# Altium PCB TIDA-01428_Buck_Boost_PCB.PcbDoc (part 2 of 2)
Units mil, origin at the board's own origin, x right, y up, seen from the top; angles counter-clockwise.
Board outline 4000 x 3000 mil, 2 copper layers (Top Layer, Bottom Layer), stack 62 mil thick; 127 components, 76 nets, 360 pads, 338 vias.
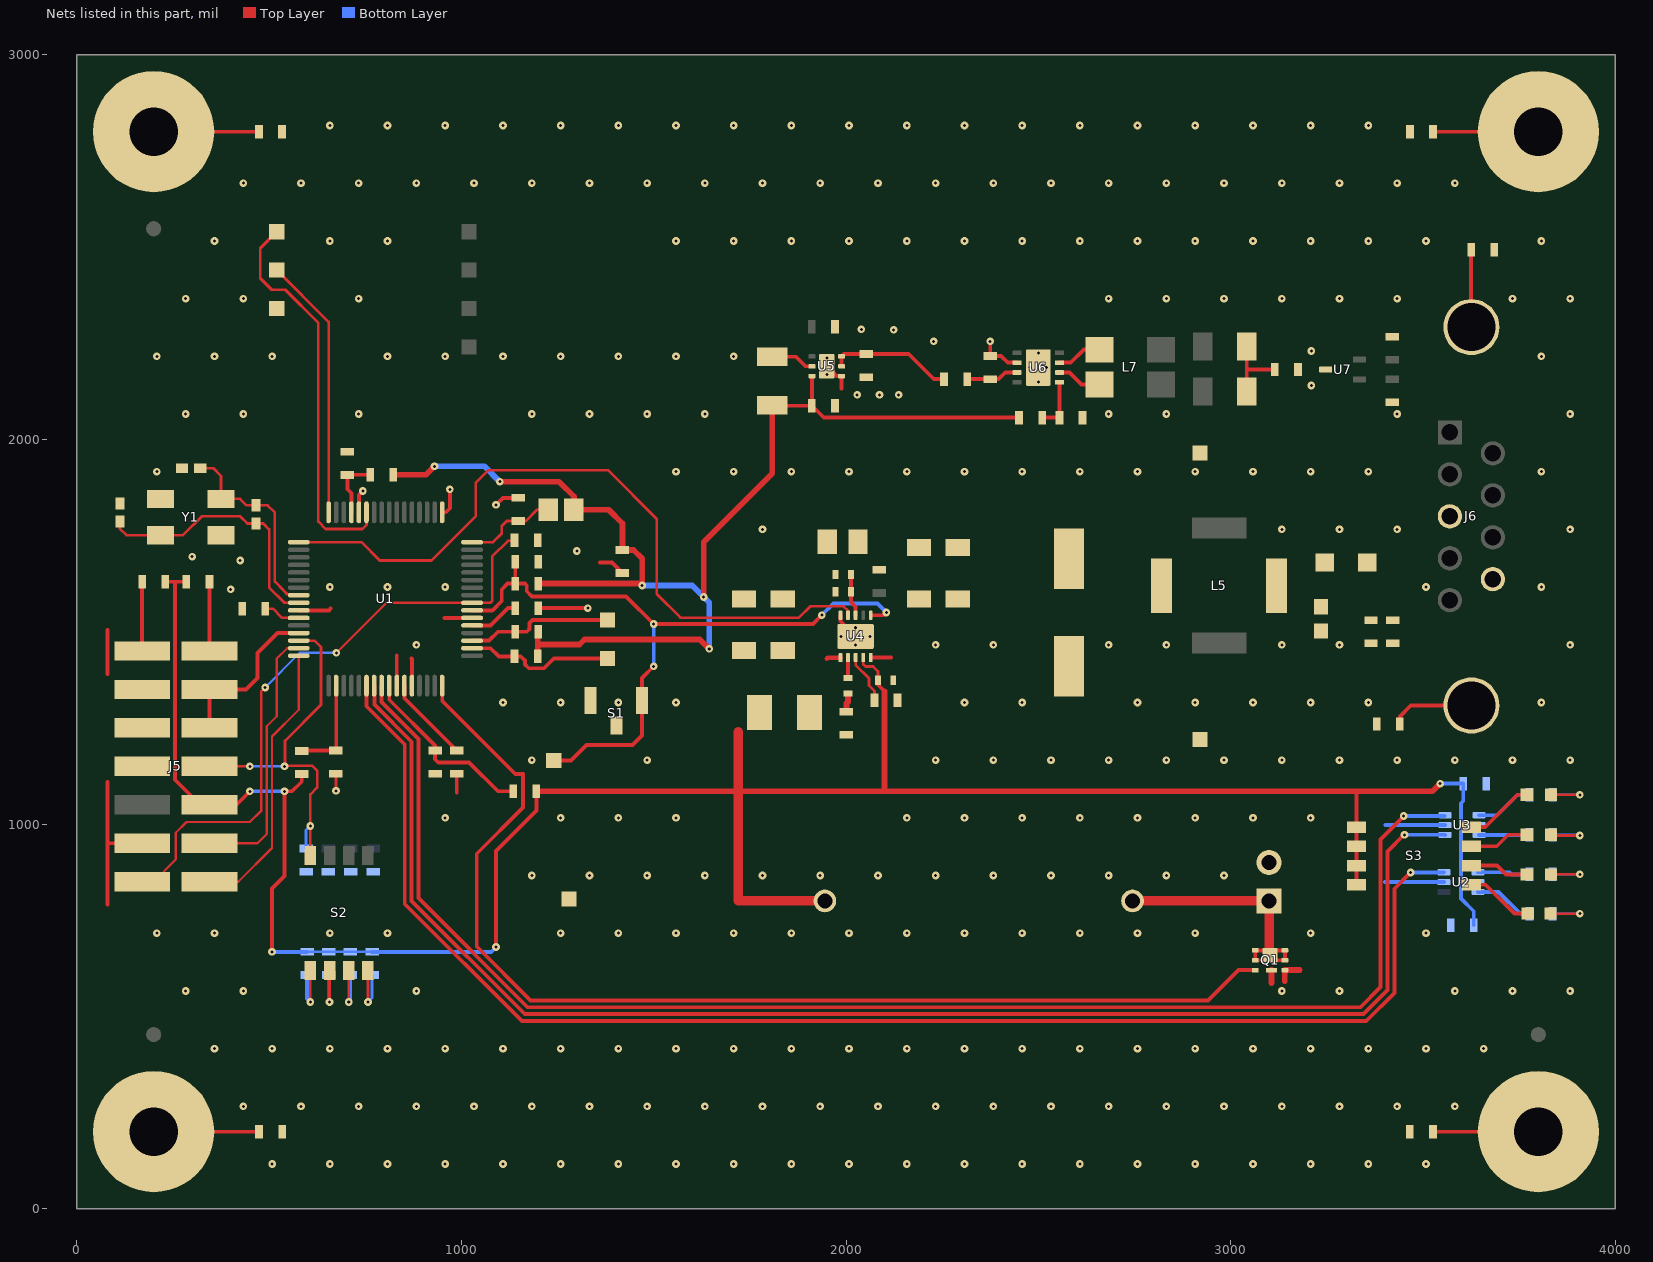
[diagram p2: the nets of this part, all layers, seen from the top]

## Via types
v1: diameter 20, hole 7.87, Top Layer to Bottom Layer, tented both sides, 328 vias
v2: diameter 19.68, hole 7.87, Top Layer to Bottom Layer, 10 vias

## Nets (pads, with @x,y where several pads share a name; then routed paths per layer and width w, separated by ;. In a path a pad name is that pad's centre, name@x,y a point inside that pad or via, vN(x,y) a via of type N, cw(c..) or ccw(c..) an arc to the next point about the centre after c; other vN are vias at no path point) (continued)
GND: C1.2 C2.2 C3.2 C4.2 C5.2 C6.2 C7.2 C8.2 C9.2 C10.2 C11.2 C13.2 C14.2 C15.2 C16.2 C17.2 C18.2 C19.2 C20.2 C21.2 C22.2 C23.2 C24.2 C25.2 C26.2 C27.2 C28.2 C29.2 C30.2 C31.2 C36.2 C37.2 J5.4 J5.8 J5.10 J5.12 J6.3 J7.2 Q1.4 Q1.7 R8.1 R9.1 R10.1 R11.1 R19.1 R20.2 R27.1 R28.1 R30.2 R31.2 R32.2 R33.2 R34.2 S1.2 S1.3 TP10.1 TP11.1 TP12.1 TP13.1 U1.6 U1.17 U1.28 U1.42 U1.58 U1.60 U2.2 U3.2 U4.5 U4.10 U4.11@2025,1487.64 U5.1 U5.7@1950,2190 U6.2 U6.9@2500,2186.69 U7.3 Y1.2 Y1.4 | length 2291.9
  Top Layer w7: v1(673.81,1086.19) R8.1@673.81,1130.91
  Top Layer w10: 80,790.25 80,950 ; 80,1110 80,950 ; 80,1390 80,1505 ; J5.4@170,950 80,950 ; U1.42@577.11,1555.54 655.54,1555.54 660,1560 ; U1.28@733.6,1810.46 733.6,1855.44 v1(743.79,1865.63) ; U1.58@832.03,1359.67 832.03,1437.97 ; 870,1430 871.4,1428.6 U1.60@871.4,1359.67 ; U1.17@950.14,1810.46 959.54,1810.46 970,1820.92 v1(970,1870) ; 955.85,1535.85 U1.6@1027.89,1535.85 ; 987.81,1082.19 C6.2@987.81,1130.91 ; v1(1090,1830) 1108,1848 C5.2@1148,1848 ; C8.2@1200,1561.31 v1(1328.69,1561.31) ; 1360,1680 1391.25,1680 C1.2@1418.75,1652.5 ; U5.7@1950,2190 1975.59,2164.41 U5.1@1988.39,2164.41 1988.39,2131.61 ; U4.10@1985.63,1542.76 1985.63,1527.01 U4.11@2025,1487.64 ; U4.5@2064.37,1432.52 2117.48,1432.52 ; v1(2375,2255) C28.2@2375,2216.69 2403.31,2216.69 2420.51,2199.49 U6.2@2444.88,2199.49
  Top Layer w15: 3106.35,586.35 Q1.7@3106.35,620.19 ; 3140.99,590.99 Q1.4@3140.99,620.19 3179.81,620.19
  Bottom Layer w10: v2(1987.6,1487.64) 2025,1487.64 ; v2(2025,1465) 2025,1487.64 ; v2(2025,1510.28) 2025,1487.64 ; v2(2062.4,1487.64) 2025,1487.64 ; v2(2478.35,2186.69) 2500,2186.69 ; v2(2500,2149.29) 2500,2186.69 ; v2(2500,2224.09) 2500,2186.69 ; v2(2521.65,2186.69) 2500,2186.69 ; 3401,849 U2.2@3554.71,849 ; 3402.19,997.19 U3.2@3557.62,997.19
  other v1: 508,116 658,116 808,116 958,116 1108,116 1258,116 1408,116 1558,116 1708,116 1858,116 2008,116 2158,116 2308,116 2458,116 2608,116 2758,116 2908,116 3058,116 3208,116 3358,116 3508,116 433,266 583,266 733,266 883,266 1033,266 1183,266 1333,266 1483,266 1633,266 1783,266 1933,266 2083,266 2233,266 2383,266 2533,266 2683,266 2833,266 2983,266 3133,266 3283,266 3433,266 3583,266 358,416 508,416 658,416 808,416 958,416 1108,416 1258,416 1408,416 1558,416 1708,416 1858,416 2008,416 2158,416 2308,416 2458,416 2608,416 2758,416 2908,416 3058,416 3208,416 3358,416 3508,416 3658,416 283,566 433,566 883,566 3133,566 3283,566 3583,566 3733,566 3883,566 208,716 358,716 658,716 808,716 1258,716 1408,716 1558,716 1708,716 1858,716 2008,716 2158,716 2308,716 2458,716 2608,716 2758,716 2908,716 3208,716 3508,716 1183,866 1333,866 1483,866 1633,866 1783,866 1933,866 2083,866 2233,866 2383,866 2533,866 2683,866 2833,866 2983,866 958,1016 1258,1016 1408,1016 1558,1016 2158,1016 2308,1016 2458,1016 2608,1016 2758,1016 2908,1016 3058,1016 3208,1016 1183,1166 1483,1166 2233,1166 2383,1166 2533,1166 2683,1166 2833,1166 2983,1166 3133,1166 3283,1166 3433,1166 3583,1166 3733,1166 3883,1166 1108,1316 1258,1316 1408,1316 1558,1316 2308,1316 2458,1316 2758,1316 2908,1316 3058,1316 3208,1316 3358,1316 3808,1316 883,1466 2233,1466 2383,1466 2683,1466 2833,1466 3133,1466 3283,1466 3883,1466 400,1610 658,1616 808,1616 958,1616 3508,1616 3808,1616 425,1685 300,1695 1300,1710 1783,1766 3133,1766 3283,1766 3433,1766 3883,1766 208,1916 1558,1916 1708,1916 1858,1916 2008,1916 2158,1916 2308,1916 2458,1916 2608,1916 2758,1916 2908,1916 3058,1916 3208,1916 3358,1916 3808,1916 283,2066 433,2066 733,2066 1183,2066 1333,2066 1483,2066 1633,2066 2683,2066 2833,2066 3433,2066 3883,2066 2029,2116 2087,2116 2137,2116 3210,2140 208,2216 358,2216 508,2216 808,2216 958,2216 1108,2216 1258,2216 1408,2216 1558,2216 1708,2216 3808,2216 3210,2230 2228,2255 2124,2285 2040,2286 283,2366 433,2366 733,2366 2683,2366 2833,2366 2983,2366 3133,2366 3283,2366 3433,2366 3733,2366 3883,2366 358,2516 658,2516 808,2516 1558,2516 1708,2516 1858,2516 2008,2516 2158,2516 2308,2516 2458,2516 2608,2516 2758,2516 2908,2516 3058,2516 3208,2516 3358,2516 3508,2516 3808,2516 433,2666 583,2666 733,2666 883,2666 1033,2666 1183,2666 1333,2666 1483,2666 1633,2666 1783,2666 1933,2666 2083,2666 2233,2666 2383,2666 2533,2666 2683,2666 2833,2666 2983,2666 3133,2666 3283,2666 3433,2666 3583,2666 658,2816 808,2816 958,2816 1108,2816 1258,2816 1408,2816 1558,2816 1708,2816 1858,2816 2008,2816 2158,2816 2308,2816 2458,2816 2608,2816 2758,2816 2908,2816 3058,2816 3208,2816 3358,2816
  other v2: 1950,2168.35 1950,2211.65
GREEN_LED: U1.54 U2.3 | length 3755.3
  Top Layer w10: U1.54@753.29,1359.67 753.29,1306.16 852.87,1206.57 852.87,792.4 1157.4,487.87 3352.6,487.87 3425.75,561.03 3425.75,831.75 v1(3468,874)
  Bottom Layer w10: v1(3468,874) 3554.12,874 U2.3@3554.71,874.59
I2C_SCL: R13.1 TP8.1 U1.3 | length 548.5
  Top Layer w10: U1.3@1027.89,1476.7 1071.7,1476.7 1095,1500 R13.1@1140,1500 1170,1500 1177.13,1507.13 1177.13,1522.83 1184.67,1530.37 1215.33,1530.37 ; 1215.33,1530.37 1215.71,1530 TP8.1@1380,1530 1379.63,1530.37 1215.33,1530.37
I2C_SDA: R12.1 TP7.1 U1.2 | length 389.9
  Top Layer w10: U1.2@1027.89,1457.11 1075.89,1457.11 1097.39,1435.61 R12.1@1138.31,1435.61 1154.39,1435.61 1165,1425 1165,1415 1175,1405 1215,1405 1240,1430 TP7.1@1380,1430
MASTER_SELECT: R5.1 R8.2 U1.50 | length 255.9
  Top Layer w10: R5.1@585.91,1190.91 R8.2@673.81,1190.91 ; R8.2@674.55,1191.64 U1.50@674.55,1359.67
NetC3_1: C3.1 L1.1 U1.57 | length 478.6
  Top Layer w10: U1.57@812.34,1359.67 812.34,1322.94 931.5,1203.78 C3.1@931.5,1190.91 931.5,1168.5 940,1160 1020,1160 1095,1085 L1.1@1135,1085
NetC4_1: C4.1 L2.1 U1.29 | length 160.7
  Top Layer w10: U1.29@713.92,1810.46 713.92,1860.08 703.75,1870.25 C4.1@703.75,1907.5 704.25,1908 L2.1@763,1908
NetC5_1: C5.1 L3.1 U1.16 | length 244.3
  Top Layer w7: U1.16@1027.89,1732.7 1082.7,1732.7 1105,1755 1105,1775 1118,1788 C5.1@1148,1788 1168,1788 1197,1817 L3.1@1225.54,1817
NetC6_1: C6.1 U1.59 | length 225.1
  Top Layer w10: U1.59@851.71,1359.67 851.71,1327 C6.1@987.81,1190.91
NetC7_1: C7.1 U1.43 | length 97.1
  Top Layer w7: C7.1@490,1560 510,1560 534.15,1535.85 U1.43@577.11,1535.85
NetC8_1: C8.1 U1.5 | length 130.8
  Top Layer w10: U1.5@1027.89,1516.07 1076.07,1516.07 1121.31,1561.31 C8.1@1140,1561.31
NetC10_1: C10.1 R16.2 U1.41 Y1.1 | length 692.4
  Top Layer w7: C10.1@112.5,1786.38 112.5,1767.5 129.09,1750.91 Y1.1@217.49,1750.91 275.91,1750.91 325,1800 425,1800 443.62,1781.38 R16.2@466.39,1781.38 484.87,1781.38 500.13,1766.12 500.13,1614.87 539.78,1575.22 U1.41@577.11,1575.22
NetC11_1: C11.1 R16.1 U1.40 Y1.3 | length 533.3
  Top Layer w7: C11.1@321.12,1925 355,1925 374.97,1905.03 Y1.3@374.97,1845.4 424.6,1845.4 441.38,1828.62 R16.1@466.39,1828.62 496.38,1828.62 515,1810 515,1630 537.19,1607.81 537.19,1607.44 547.31,1597.31 574.7,1597.31 U1.40@577.11,1594.91
NetC12_1: C12.1 R35.2 | length 48.9
  Top Layer w15: C12.1@2001,1292 2001,1313 2005,1317 R35.2@2005,1339.26
NetC12_2: C12.2 L6.1 U4.1 | length 36.7
  Top Layer w12: 1950,1430 1952.52,1432.52 U4.1@1985.63,1432.52
NetC15_1: C15.1 D5.1 L5.1
NetC19_1: C19.1 U4.3 | length 130.9
  Top Layer w7: U4.3@2025,1432.52 2025,1413.97 2060,1378.97 2060,1360 2073.98,1346.02 C19.1@2073.98,1321.89
NetC27_1: C27.1 R23.1 R24.2 | length 188.8
  Top Layer w10: R24.2@3042.09,2124.45 R23.1@3042.09,2241.69 ; 3043.46,2181.69 C27.1@3115,2181.69
NetC28_1: C28.1 R21.2 U6.3 | length 137
  Top Layer w10: R21.2@2315,2156.69 C28.1@2375,2156.69 2396.69,2156.69 2413.9,2173.9 U6.3@2444.88,2173.9
NetC29_1: C29.1 R22.2 U6.5 | length 136.7
  Top Layer w10: R22.2@2510,2056.69 C29.1@2555,2056.69 2555.12,2056.81 U6.5@2555.12,2148.31
NetD1_1: D1.1 S3.1 | length 177.1
  Top Layer w10: S3.1@3626.41,842 3663,842 3738,767 D1.1@3772.47,767
NetD1_2: D1.2 R1.2 | length 147.4
  Top Layer w7: D1.2@3831.53,767 v1(3908,767)
  Bottom Layer w7: R1.2@3837.07,767 v1(3908,767)
NetD2_1: D2.1 R2.2 | length 145.9
  Top Layer w7: D2.1@3833.06,868.99 v1(3908,869)
  Bottom Layer w7: R2.2@3837.07,869 v1(3908,869)
NetD2_2: D2.2 S3.2 | length 153.2
  Top Layer w10: S3.2@3626.41,892 3693,892 3716.01,868.99 D2.2@3770.07,868.99
NetD3_1: D3.1 R3.2 | length 144.7
  Top Layer w7: D3.1@3835.06,970 v1@3905,970 ; v1@3907,972 v1@3905,970 ; v1(3908,970) v1@3905,970
  Bottom Layer w7: R3.2@3837.07,972 v1@3906,972
NetD3_2: D3.2 S3.3 | length 156.1
  Top Layer w10: S3.3@3626.41,942 3692,942 3722,972 D3.2@3770.07,972
NetD4_1: D4.1 R4.2 | length 145.9
  Top Layer w7: D4.1@3833.06,1076 v1(3908,1076)
  Bottom Layer w7: R4.2@3837.07,1076.01 v1(3908,1076)
NetD4_2: D4.2 S3.4 | length 178.5
  Top Layer w10: S3.4@3626.41,992 3662,992 3746,1076 D4.2@3770.07,1076
NetH1_1: H1.1 R31.1 | length 273.8
  Top Layer w10: H1.1@200,2800 R31.1@473.75,2800
NetH2_1: H2.1 R32.1 | length 273.8
  Top Layer w10: R32.1@3526.25,2800 H2.1@3800,2800
NetH3_1: H3.1 R33.1 | length 273.8
  Top Layer w10: H3.1@200,200 R33.1@473.75,200
NetH4_1: H4.1 R34.1 | length 273.8
  Top Layer w10: R34.1@3526.25,200 H4.1@3800,200
NetJ5_13: J5.13 R14.1 | length 180
  Top Layer w10: J5.13@345,1450 R14.1@345,1630
NetJ5_14: J5.14 R15.1 | length 180
  Top Layer w10: J5.14@170,1450 R15.1@170,1630
NetJ6_10: J6.10 R20.1 | length 199.7
  Top Layer w10: J6.10@3625,2292.91 R20.1@3625,2492.57
NetJ6_11: J6.11 R30.1 | length 217.4
  Top Layer w10: R30.1@3440.11,1260 3440.11,1279.89 3468.29,1308.07 J6.11@3625.98,1308.07
NetJ7_1: J7.1 Q1.1 Q1.2 Q1.5 Q1.6 Q1.8 R29.1 | length 688.4
  Top Layer w10: Q1.2@3064.22,645.78 Q1.5@3140.99,645.78 Q1.6@3140.99,671.37 3100,671.37 Q1.1@3064.22,671.37 Q1.2@3064.22,645.78
  Top Layer w25: R29.1@2745,800 J7.1@3100,800 Q1.8@3100,671.37
NetL4_2: L4.2 U5.5 | length 113.4
  Top Layer w10: L4.2@1808.48,2214.85 1870.15,2214.85 1895,2190 U5.5@1911.61,2190
NetL7_1: L7.1 U6.6 | length 116.9
  Top Layer w10: U6.6@2555.12,2173.9 2581.1,2173.9 2612.19,2142.81 L7.1@2659.17,2142.81
NetL7_4: L7.4 U6.7 | length 118.1
  Top Layer w10: U6.7@2555.12,2199.49 2584.49,2199.49 2618.36,2233.36 L7.4@2659.17,2233.36
NetR1_1: R1.1 U2.6 | length 157.1
  Bottom Layer w10: U2.6@3643.29,823.4 3696.6,823.4 3753,767 R1.1@3777.07,767
NetR2_1: R2.1 U2.4 | length 136.1
  Bottom Layer w10: U2.4@3643.29,874.59 3725.41,874.59 3731,869 R2.1@3777.07,869
NetR3_1: R3.1 U3.6 | length 131
  Bottom Layer w10: U3.6@3646.21,971.6 3776.67,971.6 R3.1@3777.07,972
NetR4_1: R4.1 U3.4 | length 152.9
  Bottom Layer w10: U3.4@3646.21,1022.78 3692.78,1022.78 3746.01,1076.01 R4.1@3777.07,1076.01
NetR6_1: R6.1 S2.8 | length 156.9
  Top Layer w7: v1(757.18,537.18) S2.8@757.18,619.41
  Bottom Layer w7: v1(757.18,537.18) 767.8,547.8 R6.1@767.8,607.51
NetR7_1: R7.1 S2.7 | length 154.3
  Top Layer w7: v1(707.18,537.18) S2.7@707.18,619.41
  Bottom Layer w7: v1(707.18,537.18) 711.49,541.49 R7.1@711.49,607.51
NetR25_1: R25.1 S2.6 | length 153.4
  Top Layer w7: v1(657.18,537.18) S2.6@657.18,619.41
  Bottom Layer w7: R25.1@655.18,607.51 655.18,539.19 v1(657.18,537.18)
NetR26_1: R26.1 S2.5 | length 156
  Top Layer w7: v1(607.18,537.18) S2.5@607.18,619.41
  Bottom Layer w10: R26.1@598.87,607.51 598.87,545.5 v1(607.18,537.18)
NetR35_1: R35.1 U4.2 | length 53.3
  Top Layer w10: R35.1@2005,1379.26 U4.2@2005.31,1432.52
NRST: C37.1 R17.2 S1.1 TP9.1 U1.7 U4.6 | length 1865.4
  Top Layer w10: U1.7@1027.99,1555.44 1080.44,1555.44 1105,1580 1105,1610 1120,1625 R17.2@1140,1625 ; C37.1@1140,1680 R17.2@1140,1625 ; TP9.1@1240,1165 1285,1165 1325,1205 1445,1205 1469.93,1229.93 S1.1@1469.93,1321 1469.93,1379.93 v1(1500,1410) ; v1(1937,1543) 1914,1520 v1(1500,1520) 1428.32,1591.68 1183.32,1591.68 1170,1605 1170,1620 1165,1625 R17.2@1140,1625 ; U4.6@2064.37,1542.76 2097.76,1542.76 v1(2105,1550)
  Bottom Layer w10: v1(1500,1410) v1(1500,1520) ; v1(1937,1543) 1967.26,1573.26 2081.74,1573.26 v1(2105,1550)
NTRST: J5.2 R11.2 U1.8 | length 1625.4
  Top Layer w6: J5.2@170,850 200,850 257.5,907.5 257.5,977.5 285,1005 450,1005 480,1035 480,1345 v1(490,1355) ; v1(675,1445) 805.22,1575.22 U1.8@1027.89,1575.22
  Top Layer w7: U1.8@1027.89,1575.22 1075.22,1575.22 1080,1580 1080,1695 1121.31,1736.31 R11.2@1138.31,1736.31
  Bottom Layer w6: v1(490,1355) 580,1445 v1(675,1445)
Q1_GATE: Q1.3 U1.64 | length 2941.6
  Top Layer w10: U1.64@950.14,1359.67 950.14,1319.86 1140,1130 1160,1130 1160,1042.79 1040,922.79 1040,681.11 1179.61,541.5 2941.5,541.5 3020.19,620.19 Q1.3@3064.22,620.19
RED_LED: U1.55 U3.1 | length 3813.5
  Top Layer w10: U1.55@772.97,1359.67 773.88,1358.77 773.88,1310.84 870.75,1213.97 870.75,799.81 1164.81,505.75 3345.19,505.75 3407.87,568.43 3407.87,928.87 3451,972 v1(3452,972)
  Bottom Layer w10: v1(3452,972) 3557.22,972 U3.1@3557.62,971.6
SYNC: U1.33 U4.9 | length 1898.3
  Top Layer w7: U1.33@577.11,1732.7 740,1732.7 787.7,1685 922,1685 1037,1800 1037,1887 1070,1920 1381,1920 1508,1793 1508,1598 1569.63,1536.37 1877.37,1536.37 1907,1566 1994.05,1566 2005.32,1554.74 U4.9@2005.32,1542.76
TCK: J5.9 J5.11 U1.45 | length 430.9
  Top Layer w10: J5.9@345,1250 J5.11@345,1350 440,1350 470,1380 470,1445 521.48,1496.48 U1.45@577.11,1496.48
TDI: J5.3 U1.47 | length 694
  Top Layer w6: J5.3@345,950 470,950 493.87,973.87 493.87,1253.87 520,1280 520,1430 547.11,1457.11 U1.47@577.11,1457.11
TDO: J5.7 R28.2 S2.4 U1.46 | length 989.5
  Top Layer w7: J5.7@345,1150 v1(450,1150) ; v1(540,1150) v1@541.25,1151.25 ; U1.46@577.11,1476.8 618.2,1476.8 635,1460 635,1310 541.25,1216.25 v1@541.25,1151.25 ; S2.4@607.18,918.23 v1(607.18,995) 607.18,1077.18 625,1095 625,1138.75 612.38,1151.37 541.37,1151.37 v1@541.25,1151.25
  Bottom Layer w7: v1(450,1150) v1(540,1150) ; R28.2@596.18,936.14 596.18,984 v1(607.18,995)
TMS: J5.1 U1.48 | length 727.5
  Top Layer w6: J5.1@345,850 420,850 507.75,937.75 507.75,1227.75 577.11,1297.11 U1.48@577.11,1437.43
UART_RX: TP3.1 U1.32 | length 685.4
  Top Layer w7: TP3.1@520,2440 654.86,2305.14 U1.32@654.86,1810.46
UART_TX: TP4.1 U1.27 | length 1025.4
  Top Layer w7: TP4.1@520,2540 477,2497 477,2419 507,2389 542,2389 628,2303 628,1786 647,1767 743,1767 753.29,1777.29 U1.27@753.29,1810.46
V3P3: C1.1 C2.1 C9.1 C20.1 C21.1 C22.1 C24.1 J5.5 L1.2 L2.2 L3.2 L4.1 L6.2 R5.2 R6.2 R7.2 R12.2 R13.2 R14.2 R15.2 R17.1 R22.1 R25.2 R26.2 R29.2 S3.5 S3.6 S3.7 S3.8 U2.5 U3.5 U4.4 U5.6 | length 9909.3
  Top Layer w7: U4.4@2044.68,1432.52 2044.68,1415.32 2050.67,1409.33 2070.67,1409.33 2082.96,1397.04 C24.1@2082.96,1373.97
  Top Layer w10: R15.2@230,1630 255,1630 ; R14.2@285,1630 255,1630 ; v1(450,1085) 415,1050 J5.5@345,1050 320.32,1050 255.32,1115 255.32,1480.65 255,1480.96 255,1630 ; v1(507.49,667.51) 507.49,832.49 540,865 v1(540,1085) 560,1085 585,1110 R5.2@585,1130 ; v1(1090,680) 1090,930 1195,1035 L1.2@1195,1085 ; L4.1@1809.85,2087.5 C22.1@1911.25,2087.5 ; U5.6@1911.61,2164.41 1911.61,2087.86 C22.1@1911.25,2087.5 ; C24.1@2082.96,1373.97 2082.96,1362.04 2100,1345 ; R22.1@2450,2056.69 1942.06,2056.69 C22.1@1911.25,2087.5 ; S3.8@3327.59,842 S3.7@3327.59,892 S3.6@3327.59,942 S3.5@3327.59,992 3327.59,1085
  Top Layer w15: L2.2@823,1908 908,1908 v1(930,1930) ; v1(1100,1890) 1254.1,1890 1292.46,1851.64 L3.2@1292.46,1817 1383,1817 1418.75,1781.25 C1.1@1418.75,1712.5 1447.5,1712.5 1470,1690 v1@1470,1625 ; L1.2@1195,1085 1715.08,1085 ; R12.2@1198.31,1435.61 1198.31,1466.96 ; R13.2@1198.31,1498.31 1198.31,1466.96 ; R17.1@1200,1625 v1@1470,1625 ; v1(1470,1620) v1@1470,1625 ; v1(1630,1590) 1630,1733.03 1808.48,1911.52 L4.1@1808.48,2088.87 ; v1(1644.42,1455.58) 1620,1480 1320,1480 1306.96,1466.96 1198.31,1466.96 ; 1720.08,1085 2100,1085 ; 2100,1345 2100,1085 ; v1(3545,1105) 3525,1085 3327.59,1085 2100,1085
  Top Layer w25: 1720.08,1239.92 1720.08,1085 1720.08,800 R29.2@1945,800
  Bottom Layer w7: R26.2@598.87,667.51 R25.2@655.18,667.51 R7.2@711.49,667.51 R6.2@767.8,667.51
  Bottom Layer w10: v1(450,1085) v1(540,1085) ; v1(507.49,667.51) R26.2@598.87,667.51 ; R6.2@767.8,667.51 1077.51,667.51 v1(1090,680) ; v1(3545,1105) C2.1@3605,1105 3605,1060 3599,1054 3599,999.37 ; 3599,997.19 3599,849 ; 3601.19,997.19 U3.5@3646.21,997.19 ; C9.1@3632,737 3632,773 3599,806 3599,849 ; U2.5@3643.29,849 3599,849
  Bottom Layer w15: v1(930,1930) 1060,1930 v1(1100,1890) ; v1(1470,1620) 1600,1620 v1(1630,1590) 1644.42,1575.58 v1(1644.42,1455.58)
V5P0: C23.1 R21.1 U5.2 U5.3 | length 321.8
  Top Layer w10: U5.2@1988.39,2190 U5.3@1988.39,2215.59 1994.66,2221.86 C23.1@2052.31,2221.86 2163.14,2221.86 2228.31,2156.69 R21.1@2255,2156.69
VBATT: C14.1 C36.1 D5.2 J6.9
VBATT_FILT: C13.1 C16.1 C17.1 C18.1 C25.1 C31.1 L5.3 R18.2 U4.8 | length 110.8
  Top Layer w10: C25.1@2013,1648.5 2012.82,1577.18 2025,1565 U4.8@2025,1542.76
YELLOW_LED: U1.56 U3.3 | length 3810
  Top Layer w10: U1.56@792.66,1359.67 792.66,1317.34 888.62,1221.38 888.62,807.21 1172.21,523.62 3337.79,523.62 3390,575.83 3390,960 3451,1021 v1(3450,1021)
  Bottom Layer w10: v1(3450,1021) U3.3@3555.85,1021
pads on no net: FID1.1 FID2.1 FID3.1 J5.6 J6.1 J6.4 J6.5 J6.6 J6.8 L5.2 L5.4 Q1.0 U1.1 U1.4 U1.9 U1.10 U1.11 U1.12 U1.13 U1.14 U1.15 U1.18 U1.19 U1.20 U1.21 U1.22 U1.23 U1.24 U1.30 U1.31 U1.36 U1.37 U1.38 U1.39 U1.44 U1.51 U1.62 U1.63 U4.11@1964.76,1477.8 U4.11@1964.76,1497.48 U4.11@2000.2,1487.64 U4.11@2049.8,1487.64 U4.11@2085.24,1477.8 U4.11@2085.24,1497.48 U5.7@1950,2172.28 U5.7@1950,2207.72 U6.9@2500,2161.69 U6.9@2500,2211.69

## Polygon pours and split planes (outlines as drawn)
GND on Bottom Layer "Bottom Layer-No Net" (solid, pour order 0): 75,75 3925,75 3925,2925 75,2925 75,75
V3P3 on Top Layer "V3p3_Pour" (solid, pour order 12): 2140,1050 2140,1200 1830,1200 1830,1350 1910,1430 1910,1490 1610,1490 1610,1050
GND on Top Layer "TOP_LAYER_GND_P014" (solid, pour order 14): 75,75 3925,75 3925,2925 75,2925 75,75
VBATT on Top Layer "Top Layer-No Net" (solid, pour order 4): 3315,1490 3315,1730 3420,1730 3420,1640 3500,1530 3620,1530 3620,1700 3760,1700 3760,1490
NetC15_1 on Top Layer "Top Layer-No Net 1" (solid, pour order 6): 3295,1730 3295,1525 3050,1525 3050,1730
VBATT_FILT on Top Layer "Top Layer-No Net 2" (solid, pour order 8): 2890,1820 2890,1530 2520,1530 2290,1680 2130,1680 2130,1640 2060,1640 2060,1620 2060,1577.18 1999,1577.18 1999,1820
NetC12_2 on Top Layer "Top Layer-No Net 3" (solid, pour order 10): 1964.96,1460 2000,1460 2000,1402.64 1984.36,1387 1984.36,1360 2050,1360 2050,1202 1850,1202 1850,1350

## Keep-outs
Keep-Out Layer:
  text ".Layer_Name" at 577,-858.49 h60

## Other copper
Top Layer:
  text ".Layer_Name" at 577,-858.49 h60
Bottom Layer:
  text ".Layer_Name" at 577,-858.49 h60

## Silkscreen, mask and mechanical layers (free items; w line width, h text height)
Top Overlay:
  region: 1600,2850 1300,2850 1300,2750 1600,2750
  lines w7: 60,2060 1560,2060 ; 1650,1030 3200,1030 ; 1650,1810 2340,1810 ; 1650,2380 2180,2380 ; 2210,2380 3460,2380 ; 2380,1810 3460,1810 ; 3250,690 3975,690 ; 3755,737 3875,737 3875,797 3755,797 ; 3864,737 3864,797 ; 3870,737 3870,797 ; 60,570 60,2180 1560,2180 1560,570 60,570 ; 1650,570 3200,570 3200,1150 1650,1150 1650,570 ; 1650,1171 2340,1171 2340,1930 1650,1930 1650,1171 ; 1650,2000 2180,2000 2180,2500 1650,2500 1650,2000 ; 2210,2000 3460,2000 3460,2500 2210,2500 2210,2000 ; 2380,1311.69 2380,1930 3460,1930 3460,1311.69 2380,1311.69 ; 3250,570 3975,570 3975,1150 3250,1150 3250,570
  text "'.PRJ_Number'.PCB_Rev-" at 600,2765 h108.27
  text "UART_TX" at 570,2520 h40
  text "CAN_STB" at 1070,2520 h40
  text "UART_RX" at 570,2420 h40
  text "CAN_TXD" at 1070,2420 h40
  text "CAN Physical Layer" at 2350,2411.69 h55
  text "5V Boost" at 1710,2410 h55
  text "GND" at 570,2320 h40
  text "CAN_RXD" at 1070,2320 h40
  text "5V_EN" at 1070,2220 h40
  text "C2000 Peripheral Conns." at 150,2100 h60
  text "GND" at 2970,1945 h40
  text "Blocking & Filtering" at 2410,1850 h55
  text "3.3V Buck" at 1730,1840 h60
  text "SCL" at 1430,1510 h40
  text "SDA" at 1430,1410 h40
  text "GND" at 2970,1200 h40
  text "NRST" at 1325.2,1147.16 h40
  text "Closed-Open" at 3275,1080 h40
  text "Load Resistor" at 2110,1060 h60
  text "BM / DR1 / DR2 / TDO" at 800,985 h40 r90
  text "GND" at 1340,785 h40
  text "Status LEDs" at 3300,600 h60
  text "Closed-Open" at 520,585 h40 r90
  text ".Layer_Name" at 577,-858.49 h60
Bottom Overlay:
  text ".Layer_Name" at 577,-858.49 h60
Top Paste:
  text ".Layer_Name" at 577,-858.49 h60
Bottom Paste:
  text ".Layer_Name" at 577,-858.49 h60
Top Solder:
  text ".Layer_Name" at 577,-858.49 h60
  text ".Layer_Name" at 577,-858.49 h60
Bottom Solder:
  text ".Layer_Name" at 577,-858.49 h60
Drill Guide:
  text ".Layer_Name" at 577,-858.49 h60
M1 Board Outline:
  the board outline again, w7
  text ".Layer_Name" at 577,-858.49 h60
M2 Board Dimensions:
  rectangle: 0,-275 125,-150
  rectangle: 125,-400 500,-275
  lines w7: 0,-275 1000,-275 ; 125,-400 125,-150 ; 250,-400 250,-150 ; 500,-400 500,-150 ; 750,-400 750,-150 ; 0,-400 1000,-400 1000,-150 0,-150 0,-400
  text ".Layer_Name" at 577,-858.49 h60
M3 3D STEP Top:
  text ".Layer_Name" at 577,-858.49 h60
M4 3D STEP Bottom:
  text ".Layer_Name" at 577,-858.49 h60
M5 Assembly Top:
  lines w10: -292,-930.17 6308,-930.17 ; -292,-726.83 6310,-726.83 ; -292,-523.5 -292,-1133.5 3713,-1133.5 6310,-1133.5 6310,-523.5 -291.5,-523.5 -291.5,-1133.5 1284,-1133.5 ; 2173,-1133.5 2173,-523.5 ; 3440,-726.83 3440,-523.5 ; 4280,-726.83 4280,-523.5 ; 4902,-1140 4902,-937.17
  text "COMPONENTS MARKED 'DNP' SHOULD NOT BE POPULATED." at 1153.5,-318.5 h60
  text "ASSEMBLY VARIANT:" at 1153,-434 h60
  text ".VariantName" at 2189,-434 h60
  text "PCB VIEWED FROM TOP SIDE" at -228.5,-655.67 h60
  text "BOARD #:" at 2248,-655.67 h60
  text ".PRJ_Number" at 2793.5,-655.67 h60
  text "REV:" at 3638,-655.67 h60
  text ".PCB_Rev" at 3929.5,-655.67 h60
  text "SVN REV:" at 4476,-655.67 h60
  text ".VersionControl_RevNumber" at 4982,-655.67 h60
  text "TID #:" at 2248,-859 h60
  text ".TID" at 2793.5,-859 h60
  text "PLOT NAME =" at -228.5,-1064.34 h60
  text ".plot_File_Name" at 577,-1064.34 h60
  text "GENERATED    :" at 2250,-1064.34 h60
  text ".Print_Date" at 3119.5,-1064.34 h60
  text ".Print_Time" at 3848.5,-1064.34 h60
  text "TEXAS INSTRUMENTS" at 5113,-1064.34 h60
M6 Assembly Bottom:
  lines w10: -292.5,-727.33 6309.5,-727.33 ; -290.5,-930.67 6309.5,-930.67 ; 1115.5,-1140.5 1115.5,-937.67 ; 1737.5,-727.33 1737.5,-524 ; 2577.5,-727.33 2577.5,-524 ; 3844.5,-1134 3844.5,-524 ; 4733.5,-1134 6309,-1134 6309,-524 -292.5,-524 -292.5,-1134 2304.5,-1134 6309.5,-1134 6309.5,-524
  text "COMPONENTS MARKED 'DNP' SHOULD NOT BE POPULATED." at 6102,-318 h60
  text ".VariantName" at 5058,-434 h60
  text "ASSEMBLY VARIANT:" at 6097,-434 h60
  text ".VersionControl_RevNumber" at 1035.5,-656.17 h60
  text "SVN REV:" at 1541.5,-656.17 h60
  text ".PCB_Rev" at 2088,-656.17 h60
  text "REV:" at 2379.5,-656.17 h60
  text ".PRJ_Number" at 3224,-656.17 h60
  text "BOARD #:" at 3769.5,-656.17 h60
  text "PCB VIEWED FROM BOTTOM SIDE" at 6246,-656.17 h60
  text ".TID" at 3224,-859.5 h60
  text "TID #:" at 3769.5,-859.5 h60
  text "TEXAS INSTRUMENTS" at 904.5,-1064.84 h60
  text ".Print_Time" at 2169,-1064.84 h60
  text ".Print_Date" at 2898,-1064.84 h60
  text "GENERATED    :" at 3767.5,-1064.84 h60
  text ".plot_File_Name" at 5440.5,-1064.84 h60
  text "PLOT NAME =" at 6246,-1064.84 h60
M9 Title Sheet:
  drawing of 57 lines, arcs and shapes, not listed
  text "1" at 739.84,8036.5 h70
  text "2" at 3235.5,8036.5 h70
  text "3" at 5724.84,8036.5 h70
  text "4" at 8231.51,8036.5 h70
  text "5" at 10730.5,8036.5 h70
  text "6" at 13235.5,8036.5 h70
  text "A" at -416.5,6893.5 h70
  text "A" at 14383.5,6893.5 h70
  text "B" at -416.5,4513.5 h70
  text "B" at 14383.5,4513.5 h70
  text "C" at -416.5,2138.5 h70
  text "C" at 14383.5,2138.5 h70
  text "PROJECT TITLE:" at 11343.5,277.5 h45
  text ".PRJ_Title" at 11393.5,144.17 h70
  text "DESIGNED FOR:" at 11343.5,-23.5 h45
  text ".PRJ_Customer" at 11393.5,-163.5 h70
  text "D" at -416.5,-231.5 h70
  text "D" at 14383.5,-231.5 h70
  text "FILE NAME:" at 11343.5,-323.5 h45
  text ".PCB_File_Name_No_Path" at 11393.5,-443.5 h70
  text "Texas Instruments (TI) and/or its licensors do not warrant the accuracy or completeness of this specification" at 6374,-605.34 h45
  text "ENGINEER:" at 11343.5,-613.5 h45
  text "LAYOUT BY:" at 12848.5,-613.5 h45
  text "or any information contained therein. TI and/or its licensors do not warrant that this design will meet" at 6329.01,-718 h45
  text ".PRJ_Engineer" at 11393.5,-768.49 h70
  text ".PCB_Layout" at 12899,-768.49 h70
  text "the specifications, will be suitable for your application or fit for any particular purpose, or will operate in" at 6329.01,-830.67 h45
  text ".Layer_Name" at 577,-858.49 h60
  text "ALTIUM DESIGNER VERSION:" at 12848.5,-923.5 h45
  text "an implementation. TI and/or its licensors do not warrant that the design is production worthy. You should" at 6329.01,-943.33 h45
  text "completely validate and test your design implementation to confirm the system functionality for your application." at 6374,-1056 h45
  text ".print_Scale" at 11393.5,-1056.83 h70
  text ".Application_BuildNumber" at 12899,-1056.83 h70
  text "1" at 739.84,-1263.5 h70
  text "2" at 3235.5,-1263.5 h70
  text "3" at 5724.84,-1263.5 h70
  text "4" at 8231.51,-1263.5 h70
  text "5" at 10730.5,-1263.5 h70
  text "6" at 13235.5,-1263.5 h70
M10 Fab Notes:
  drawing of 173 lines, arcs and shapes, not listed
  text "DESIGN INFORMATION" at 12378.02,6201 h60
  text "MIN. TRACK WIDTH:" at 11733.46,6021 h60
  text "8" at 12829.7,6021 h60
  text "MIL" at 12984.46,6021 h60
  text "MIN. CLEARANCE:" at 11733.46,5889 h60
  text "0.2" at 12769.7,5889 h60
  text "mm" at 12984.46,5889 h60
  text "MIN. VIA PAD SIZE:" at 11733.46,5757 h60
  text "24" at 12799.71,5757 h60
  text "MIL" at 12984.46,5757 h60
  text "0.05mm (2MIL)" at 12428.46,5615.29 h60
  text "MINIMUM ANNULAR RING" at 11404.23,5611 h60
  text "EXTERNAL" at 13136.46,5611 h60
  text "PER" at 11604.23,5493 h60
  text "IPC-D-275 CLASS 2 LEVEL C" at 11824.23,5493 h60
  text "MIL, HOLES" at 13312.46,5380.71 h60
  text "+/-" at 12920,5380 h60
  text "+/-" at 13774,5380 h60
  text "REGISTRATION TOLERANCES:" at 11404.23,5375 h60
  text "METAL" at 12604,5375 h60
  text "5" at 13180.2,5375 h60
  text "3" at 14013.2,5375 h60
  text "MIL" at 14129.46,5375 h60
  text "+/-" at 13774,5262 h60
  text "HOLE SIZE TOLERANCE (UNLESS OTHERWISE SPECIFIED):" at 11404.23,5257 h60
  text "3" at 14013.2,5257 h60
  text "MIL" at 14129.46,5257 h60
  text "MATERIAL:" at 11329.46,5047.54 h60
  text "FR-4 High Tg" at 12315.9,4907.21 h60
  text "FR-408" at 11750.46,4898.64 h60
  text "OTHER" at 13238.46,4898.64 h60
  text "X" at 12161,4895 h60
  text "62 MIL (1.6mm) +/-10%" at 12070.56,4735.92 h60
  text "THICKNESS:" at 11404.23,4731.64 h60
  text "X" at 11942.4,4731.64 h60
  text "OTHER" at 13355.46,4731.64 h60
  text "TOLERANCE:" at 11404.23,4573.64 h60
  text "X" at 12243.53,4573.64 h60
  text "ANSI IPC-6012 TYPE 3 CLASS 2" at 12430.48,4573.64 h60
  text "OTHER +/-" at 12430.46,4417.64 h60
  text "BOW & TWIST:" at 11404.23,4260.64 h60
  text "X" at 12243.53,4260.64 h60
  text "ANSI IPC-6012 TYPE 3 CLASS 2" at 12430.48,4260.64 h60
  text "OTHER +/-" at 12430.46,4102.13 h60
  text "DRILLING:" at 11329.46,3963.64 h60
  text "REFERENCE:" at 11404.23,3846.64 h60
  text "X" at 12052.46,3846.64 h60
  text "AS SHOWN" at 12239.46,3846.64 h60
  text "X" at 12953.46,3846.64 h60
  text "NC_DRILL FILES" at 13090.46,3846.64 h60
  text "PTH COPPER THICKNESS:" at 11404.23,3688.64 h60
  text "X" at 12534.46,3688.64 h60
  text "20-30 um" at 12671.46,3688.64 h60
  text "OTHER" at 13388.46,3688.64 h60
  text "BOARD FINISH:" at 11329.46,3529.64 h60
  text "SILKSCREEN:" at 11484.68,3411.64 h60
  text "X" at 12433.46,3411.64 h60
  text "TOP" at 12559.46,3411.64 h60
  text "X" at 12943.46,3411.64 h60
  text "BOTTOM" at 13070.46,3411.64 h60
  text "SILKSCREEN COLOR:" at 11484.68,3244.64 h60
  text "X" at 12432.42,3244.64 h60
  text "WHITE" at 12559.46,3244.64 h60
  text "OTHER" at 13070.46,3244.64 h60
  text "X" at 12563.42,3085.44 h60
  text "GREEN" at 12690.46,3085.44 h60
  text "OTHER" at 13308.46,3085.44 h60
  text "SOLDER RESIST COLOR:" at 11484.68,3074.64 h60
  text "X" at 12563.42,2915.44 h60
  text "MATTE" at 12690.46,2915.44 h60
  text "SEMI-GLOSS" at 13308,2914.8 h60
  text "IMMERSION GOLD (ENIG)" at 12390.46,2726.92 h60
  text "ENEPIG" at 13728,2723.64 h60
  text "SURFACE FINISH:" at 11329.46,2722.64 h60
  text "X" at 12203.51,2722.64 h60
  text "IMM. TIN/SILVER OR EQUIV" at 11659,2565.64 h60
  text "OTHER" at 13090.46,2565.64 h60
  text "ARRAY/PANEL:" at 11329.46,2386.64 h60
  text "CUT AND TRIM PER M1 BOARD OUTLINE" at 12390.46,2382.35 h60
  text "N.C. ROUTE" at 12390.46,2230.64 h60
  text "X" at 13069.46,2230.64 h60
  text "V. SCORE" at 13256.46,2230.64 h60
  text "CERTIFICATION:" at 11329.46,2093.64 h60
  text "MATERIALS AND WORKMANSHIP FOR ALL PCBS" at 12054.46,2093.64 h60
  text "TO MEET OR EXCEED THE REQUIREMENTS OF:" at 12054.46,1995.64 h60
  text "X" at 11680.96,1859.13 h60
  text "ANSI IPC-A-600F CLASS ->" at 11819.96,1859.13 h60
  text "X" at 13459.02,1859.13 h60
  text "2" at 13577.96,1859.14 h60
  text "1" at 13262.96,1857.64 h60
  text "3" at 13931.96,1857.64 h60
  text "X" at 12495.02,1699.64 h60
  text "RoHS" at 12631.96,1699.64 h60
  text "OTHER" at 13276.36,1699.64 h60
  text "PER ORDER" at 13673.42,1699.64 h60
  text "ALL BOARDS MUST MEET OR EXCEED UL94-V0 REQUIREMENTS." at 11357,1534 h60
  text "PCB MUST BEAR THE UL94V-0 UL REGISTERED MATERIAL ID NUMBER" at 11357,1414 h60
  text "ADDITIONAL REQUIREMENTS:" at 11329.46,1240.64 h60
  text "MICROSECTION:" at 11404.23,1125.64 h60
  text "YES" at 12309.96,1125.64 h60
  text "REQUIRED" at 13171.46,969.49 h60
  text "BARE BOARD ELEC. TEST:" at 11404.23,966.64 h60
  text "NONE" at 12709.96,966.64 h60
  text "X" at 13044.46,966.64 h60
  text "PER ORDER" at 13763.46,966.64 h60
  text ".Layer_Name" at 577,-858.49 h60
M11 Gerber Information:
  lines w10: -292,-930.17 6308,-930.17 ; -292,-726.83 6310,-726.83 ; -292,-523.5 -292,-1133.5 3713,-1133.5 6310,-1133.5 6310,-523.5 -291.5,-523.5 -291.5,-1133.5 1284,-1133.5 ; 2173,-1133.5 2173,-523.5 ; 3440,-726.83 3440,-523.5 ; 4280,-726.83 4280,-523.5 ; 4902,-1140 4902,-937.17
  text "ALL ARTWORK VIEWED FROM TOP SIDE" at -228.5,-655.67 h60
  text "BOARD #:" at 2248,-655.67 h60
  text ".PRJ_Number" at 2793.5,-655.67 h60
  text "REV:" at 3638,-655.67 h60
  text ".PCB_Rev" at 3929.5,-655.67 h60
  text "SVN REV:" at 4476,-655.67 h60
  text ".VersionControl_RevNumber" at 4982,-655.67 h60
  text "LAYER NAME =" at -228.5,-858.49 h60
  text "TID #:" at 2248,-859 h60
  text ".TID" at 2793.5,-859 h60
  text "PLOT NAME =" at -228.5,-1064.34 h60
  text ".plot_File_Name" at 577,-1064.34 h60
  text "GENERATED    :" at 2250,-1064.34 h60
  text ".Print_Date" at 3119.5,-1064.34 h60
  text ".Print_Time" at 3848.5,-1064.34 h60
  text "TEXAS INSTRUMENTS" at 5113,-1064.34 h60
M12 Stackup:
  drawing of 191 lines, arcs and shapes, not listed
  text "Layer" at 9790.34,7830 h60
  text "Name" at 10200.26,7830 h60
  text "Material" at 11130,7830 h60
  text "Thickness" at 11989.77,7830 h60
  text "Constant" at 12639.6,7830 h60
  text "Board Layer Stack" at 13209.46,7830 h60
  text "1" at 9790.34,7710 h60
  text "Top Overlay" at 10200.26,7710 h60
  text "2" at 9790.34,7590 h60
  text "Top Solder" at 10200.26,7590 h60
  text "Solder Resist" at 11130,7590 h60
  text "0.40mil" at 11989.77,7590 h60
  text "3.5" at 12639.6,7590 h60
  text "3" at 9790.34,7470 h60
  text "Top Layer" at 10200.26,7470 h60
  text "Copper" at 11130,7470 h60
  text "1.40mil" at 11989.77,7470 h60
  text "4" at 9790.34,7350 h60
  text "Dielectric1" at 10200.26,7350 h60
  text "FR-4" at 11130,7350 h60
  text "59.20mil" at 11989.77,7350 h60
  text "4.8" at 12639.6,7350 h60
  text "5" at 9790.34,7230 h60
  text "Bottom Layer" at 10200.26,7230 h60
  text "Copper" at 11130,7230 h60
  text "1.40mil" at 11989.77,7230 h60
  text "6" at 9790.34,7110 h60
  text "Bottom Solder" at 10200.26,7110 h60
  text "Solder Resist" at 11130,7110 h60
  text "0.40mil" at 11989.77,7110 h60
  text "3.5" at 12639.6,7110 h60
  text "7" at 9790.34,6990 h60
  text "Bottom Overlay" at 10200.26,6990 h60
  text ".Layer_Name" at 577,-858.49 h60
M13 Component Bodies Top:
  text ".Layer_Name" at 577,-858.49 h60
M14 Component Bodies Bottom:
  text ".Layer_Name" at 577,-858.49 h60
M15 Courtyards Top:
  text ".Layer_Name" at 577,-858.49 h60
M16 Courtyards Bottom:
  text ".Layer_Name" at 577,-858.49 h60
Drill Drawing:
  circle w10: c9972.32,6178.97 r27.67
  lines w10: 9944.65,6289.64 9958.49,6289.64 9958.49,6275.81 9986.15,6275.81 9986.15,6289.64 9999.99,6289.64 9999.99,6317.31 9986.15,6317.31 9986.15,6331.14 9958.49,6331.14 9958.49,6317.31 9944.65,6317.31 9944.65,6289.64 ; 9944.65,6400.31 9972.32,6414.14 9999.99,6400.31 9986.15,6427.97 9999.99,6455.64 9972.32,6441.81 9944.65,6455.64 9958.49,6427.97 9944.65,6400.31 ; 9944.65,6524.81 9944.65,6538.64 9958.49,6552.47 9944.65,6566.31 9944.65,6580.14 9958.49,6580.14 9972.32,6566.31 9986.15,6580.14 9999.99,6580.14 9999.99,6566.31 9986.15,6552.47 9999.99,6538.64 9999.99,6524.81 9986.15,6524.81 9972.32,6538.64 9958.49,6524.81 9944.65,6524.81 ; 9944.65,6663.14 9958.49,6663.14 9972.32,6649.31 9986.15,6663.14 9999.99,6663.14 9986.15,6676.97 9999.99,6690.81 9986.15,6690.81 9972.32,6704.64 9958.49,6690.81 9944.65,6690.81 9958.49,6676.97 9944.65,6663.14
  lines w12: 9894.49,6113.96 13126.68,6113.96 ; 9894.49,6736.46 13126.68,6736.46 ; 10232.5,5989.46 10232.5,6860.96 ; 10564.66,5989.46 10564.66,6860.96 ; 11201.14,5989.46 11201.14,6860.96 ; 11460.34,5989.46 11460.34,6860.96 ; 11835.58,5989.46 11835.58,6860.96 ; 12560.13,5989.46 12560.13,6860.96 ; 9894.49,5989.46 13126.68,5989.46 13126.68,6860.96 9894.49,6860.96 9894.49,5989.46
  text "Symbol" at 9969.19,6773.81 h72
  text "Quantity" at 10269.85,6773.81 h72
  text "Finished Hole Size" at 10602.01,6773.81 h72
  text "Plated" at 11238.49,6773.81 h72
  text "Hole Type" at 11497.69,6773.81 h72
  text "Drill Layer Pair" at 11872.93,6773.81 h72
  text "Hole Tolerance" at 12597.48,6773.81 h72
  text "338" at 10269.85,6649.31 h60
  text "7.87mil (0.200mm)" at 10602.01,6649.31 h60
  text "PTH" at 11238.49,6649.31 h60
  text "Round" at 11497.69,6649.31 h60
  text "Top Layer - Bottom Layer" at 11872.93,6649.31 h60
  text "4" at 10269.85,6524.81 h60
  text "39.37mil (1.000mm)" at 10602.01,6524.81 h60
  text "PTH" at 11238.49,6524.81 h60
  text "Round" at 11497.69,6524.81 h60
  text "Top Layer - Bottom Layer" at 11872.93,6524.81 h60
  text "9" at 10269.85,6400.31 h60
  text "42.91mil (1.090mm)" at 10602.01,6400.31 h60
  text "PTH" at 11238.49,6400.31 h60
  text "Round" at 11497.69,6400.31 h60
  text "Top Layer - Bottom Layer" at 11872.93,6400.31 h60
  text "2" at 10269.85,6275.81 h60
  text "125.20mil (3.180mm)" at 10602.01,6275.81 h60
  text "PTH" at 11238.49,6275.81 h60
  text "Round" at 11497.69,6275.81 h60
  text "Top Layer - Bottom Layer" at 11872.93,6275.81 h60
  text "4" at 10269.85,6151.31 h60
  text "125.98mil (3.200mm)" at 10602.01,6151.31 h60
  text "PTH" at 11238.49,6151.31 h60
  text "Round" at 11497.69,6151.31 h60
  text "Top Layer - Bottom Layer" at 11872.93,6151.31 h60
  text "357 Total" at 10269.85,6026.81 h60
  text ".Layer_Name" at 577,-858.49 h60
M17 Embedded Cavity:
  text ".Layer_Name" at 577,-858.49 h60
M18 Embedded Assembly:
  text ".Layer_Name" at 577,-858.49 h60
M19 Embedded Keepout:
  text ".Layer_Name" at 577,-858.49 h60

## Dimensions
0,3000 to 0,0 on M2 Board Dimensions
0,0 to 4000,0 on M2 Board Dimensions
0,-400 to 1000,-400 on M2 Board Dimensions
